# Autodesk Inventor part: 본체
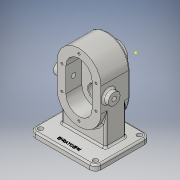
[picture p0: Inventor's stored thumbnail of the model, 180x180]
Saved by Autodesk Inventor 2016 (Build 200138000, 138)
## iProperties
Created: 2020-09
Part Number: 본체
Material: 알루미늄 6061
Document SubType Name: Modeling
Designer: Windows7
Mass: 1440.46 g
Surface Area: 785.634 cm^2
Volume: 533.505 cm^3
Density: 2.7 g/cm^3
Appearance: 알루미늄 - 평지
Author: Windows7
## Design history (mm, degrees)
sketch "스케치1"
  geometry: L1 (0, -31.193)-(0, -75.193); L2 (-40, -31.193)-(-40, -75.193); L3 (40, -75.193)-(40, -31.193); A1 r 40 centre (0, -31.193) between (40, -31.193) and (-40, -31.193); A2 r 40 centre (0, -75.193) between (-40, -75.193) and (40, -75.193); 2 further points
  constraints: 8 end point, 4 point on circle, 4 tangent, 2 centre point, 1 midpoint, 1 parallel, 1 vertical
  dimensions: "d1" = 40 radius of A1; "d2" = 44 distance of L1.end L1.start
extrude "돌출1" new body sketch "스케치1" distance "d3" = 53; taper "d4" = 0 deg
node "작업 평면4"
  node "작업 평면3"
sketch "스케치2"
  geometry: L1 (50, -17)-(-50, -17); L2 (-60, -7)-(-60, 73); L3 (-50, 83)-(50, 83); L4 (60, 73)-(60, -7); L5 (40, 0)-(40, 53) reference; A1 r 10 centre (50, -7) between (50, -17) and (60, -7); A2 r 10 centre (-50, -7) between (-60, -7) and (-50, -17); A3 r 10 centre (-50, 73) between (-50, 83) and (-60, 73); A4 r 10 centre (50, 73) between (60, 73) and (50, 83); 1 further point
  constraints: 8 end point, 8 point on circle, 8 tangent, 4 centre point, 3 equal radius, 2 parallel, 1 horizontal, 1 perpendicular
  dimensions: "d6" = 100 distance between parallel lines of L3 L1; "d7" = 120 distance between parallel lines of L2 L4; "d8" = 20 distance between parallel lines of L5 L4; "d9" = 17 distance from line of point (0, 0) L1; "d10" = 10 radius of A1
extrude "돌출2" join sketch "스케치2" distance "d11" = 10; taper "d12" = 0 deg
sketch "스케치3"
  geometry: L1 (-40, -8)-(40, -8); L2 (40, -8)-(40, -45); L3 (40, -45)-(-40, -45); L4 (-40, -45)-(-40, -8); L5 (-60, -73)-(-60, 7) reference; L6 (-50, 17)-(50, 17) reference; 1 further point
  constraints: 8 end point, 2 parallel, 1 horizontal, 1 perpendicular
  dimensions: "d13" = 37 distance between parallel lines of L3 L1; "d14" = 80 distance between parallel lines of L2 L4; "d15" = 20 distance between parallel lines of L5 L4; "d16" = 25 distance between parallel lines of L6 L1
extrude "돌출3" join sketch "스케치3" stored distance "d17" = 10; taper "d18" = 0 deg
sketch "스케치4"
  geometry: L1 (0, -31.193)-(0, -75.193); L2 (-24, -31.193)-(-24, -75.193); L3 (24, -75.193)-(24, -31.193); A1 r 40 centre (0, -31.193) between (40, -31.193) and (-40, -31.193) reference; A2 r 40 centre (0, -75.193) between (-40, -75.193) and (40, -75.193) reference; A3 r 24 centre (0, -31.193) between (24, -31.193) and (-24, -31.193); A4 r 24 centre (0, -75.193) between (-24, -75.193) and (24, -75.193); 2 further points
  constraints: 8 end point, 4 point on circle, 4 tangent, 2 centre point, 1 midpoint, 1 parallel, 1 vertical
  dimensions: "d19" = 24 radius of A3
extrude "돌출4" cut sketch "스케치4" distance "d20" = 29; taper "d21" = 0 deg
sketch "스케치5"
  geometry: C1 r 19 at (0, -31.193); A1 r 40 centre (0, -31.193) between (40, -31.193) and (-40, -31.193) reference; 1 further point
  constraints: 1 centre point, 1 coincident
  dimensions: "d22" = 38 diameter of C1
extrude "돌출5" join sketch "스케치5" distance "d23" = 17; taper "d24" = 0 deg
sketch "스케치6"
  geometry: C1 r 19 at (0, 0) reference; C2 r 14 at (0, 0); 1 further point
  constraints: 1 centre point, 1 coincident
  dimensions: "d25" = 28 diameter of C2
extrude "돌출6" cut sketch "스케치6" distance "d26" = 7.3; taper "d27" = 0 deg
sketch "스케치7"
  geometry: C1 r 14 at (0, 0) reference; C2 r 8.5 at (0, 0); 1 further point
  constraints: 1 centre point, 1 coincident
  dimensions: "d28" = 17 diameter of C2
extrude "돌출7" cut sketch "스케치7" stored distance "d29" = 7.3; taper "d30" = 0 deg
sketch "스케치8"
  geometry: C1 r 8.5 at (0, -31.193) reference; C2 r 12.5 at (0, -31.193); 1 further point
  constraints: 1 centre point, 1 coincident
  dimensions: "d31" = 25 diameter of C2
extrude "돌출8" cut sketch "스케치8" distance "d32" = 15; taper "d33" = 0 deg
sketch "스케치9"
  geometry: C1 r 12.5 at (0, -75.193); A1 r 24 centre (0, -75.193) between (-24, -75.193) and (24, -75.193) reference; 1 further point
  constraints: 1 centre point, 1 coincident
  dimensions: "d34" = 25 diameter of C1
extrude "돌출9" cut sketch "스케치9" distance "d35" = 15; taper "d36" = 0 deg
sketch "스케치10"
  geometry: L1 (0, -31.193)-(0, -75.193); L2 (-31, -31.193)-(-31, -75.193); L3 (31, -75.193)-(31, -31.193); A1 r 24 centre (0, -31.193) between (24, -31.193) and (-24, -31.193) reference; A2 r 24 centre (0, -75.193) between (-24, -75.193) and (24, -75.193) reference; A3 r 31 centre (0, -31.193) between (31, -31.193) and (-31, -31.193); A4 r 31 centre (0, -75.193) between (-31, -75.193) and (31, -75.193); 8 further points
  constraints: 8 end point, 7 point on circle, 4 tangent, 3 coincident, 2 centre point, 1 midpoint, 1 parallel, 1 vertical, 1 vertical alignment
  dimensions: "d37" = 31 radius of A3
hole "구멍1" sketch "스케치10" at (0, -0.193), (31, -75.193), (-31, -75.193), (0, -106.193), (-31, -31.193), (31, -31.193) diameter "d38" = 4.134; stored, may be unused: countersink angle "d42" = 90 deg, drill point angle "d44" = 118 deg; dims "d39" = 10, "d40" = 4, "d41" = 2, "d43" = 12
sketch "스케치11"
  geometry: L1 (-53, 0)-(-53, 44) reference; L2 (0, 44)-(-53, 44) reference; C1 r 11 at (-39, 22); 1 further point
  constraints: 1 centre point
  dimensions: "d45" = 22 diameter of C1; "d46" = 14 distance from line of L1 C1.centre; "d47" = 22 distance from line of L2 C1.centre
extrude "돌출10" join sketch "스케치11" distance "d48" = 10; taper "d49" = 0 deg
sketch "스케치12"
  geometry: 1 further point
sketch "스케치13"
  geometry: C1 r 4.5 at (-50, -73); A1 r 10 centre (-50, -73) between (-60, -73) and (-50, -83) reference; 1 further point
  constraints: 1 centre point, 1 coincident
  dimensions: "d59" = 9 diameter of C1
extrude "돌출11" cut sketch "스케치13" stored distance "d60" = 10; taper "d61" = 0 deg
sketch "스케치14"
  geometry: C1 r 4.5 at (-50, 7); A1 r 10 centre (-50, 7) between (-50, 17) and (-60, 7) reference; 1 further point
  constraints: 1 centre point, 1 coincident
  dimensions: "d62" = 9 diameter of C1
extrude "돌출12" cut sketch "스케치14" distance "d63" = 10; taper "d64" = 0 deg
chamfer "모따기1" distance "d65" = 1; stored, may be unused: second distance "d66" = 2, angle "d67" = 45 deg
fillet "모깎기1" dims "d68" = 0.5
fillet "모깎기2" dims "d72" = 3
fillet "모깎기3" dims "d73" = 3
fillet "모깎기4" dims "d74" = 3
fillet "모깎기5" dims "d75" = 3
sketch "스케치15"
  geometry: L1 (-50, -83)-(50, -83) reference; L2 (-60, 7)-(-60, -73) reference; 2 further points
  constraints: 1 other
  dimensions: "d76" = 12 distance from line of L1 point (0, -71); "d77" = 60 distance from line of point (0, -71) L2
feature "엠보싱1" sketch "스케치15" dims "d1" = 40, "d2" = 44, "d6" = 100, "d7" = 120, "d8" = 20, "d9" = 17, "d10" = 10, "d78" = 0.5, "d79" = 0
sketch "스케치16"
  geometry: 1 further point
hole "구멍3" diameter "d82" = 8.376; stored, may be unused: countersink angle "d86" = 90 deg, drill point angle "d88" = 118 deg; dims "d80" = 10, "d81" = 10, "d83" = 150, "d84" = 4, "d85" = 2, "d87" = 27.3
chamfer "모따기3" distance "d89" = 0.7; stored, may be unused: second distance "d90" = 2, angle "d91" = 30 deg
node "솔리드1"
mirror "대칭1"
mirror "대칭2"
mirror "대칭3"
node "작업 평면1"
node "작업 평면2"
